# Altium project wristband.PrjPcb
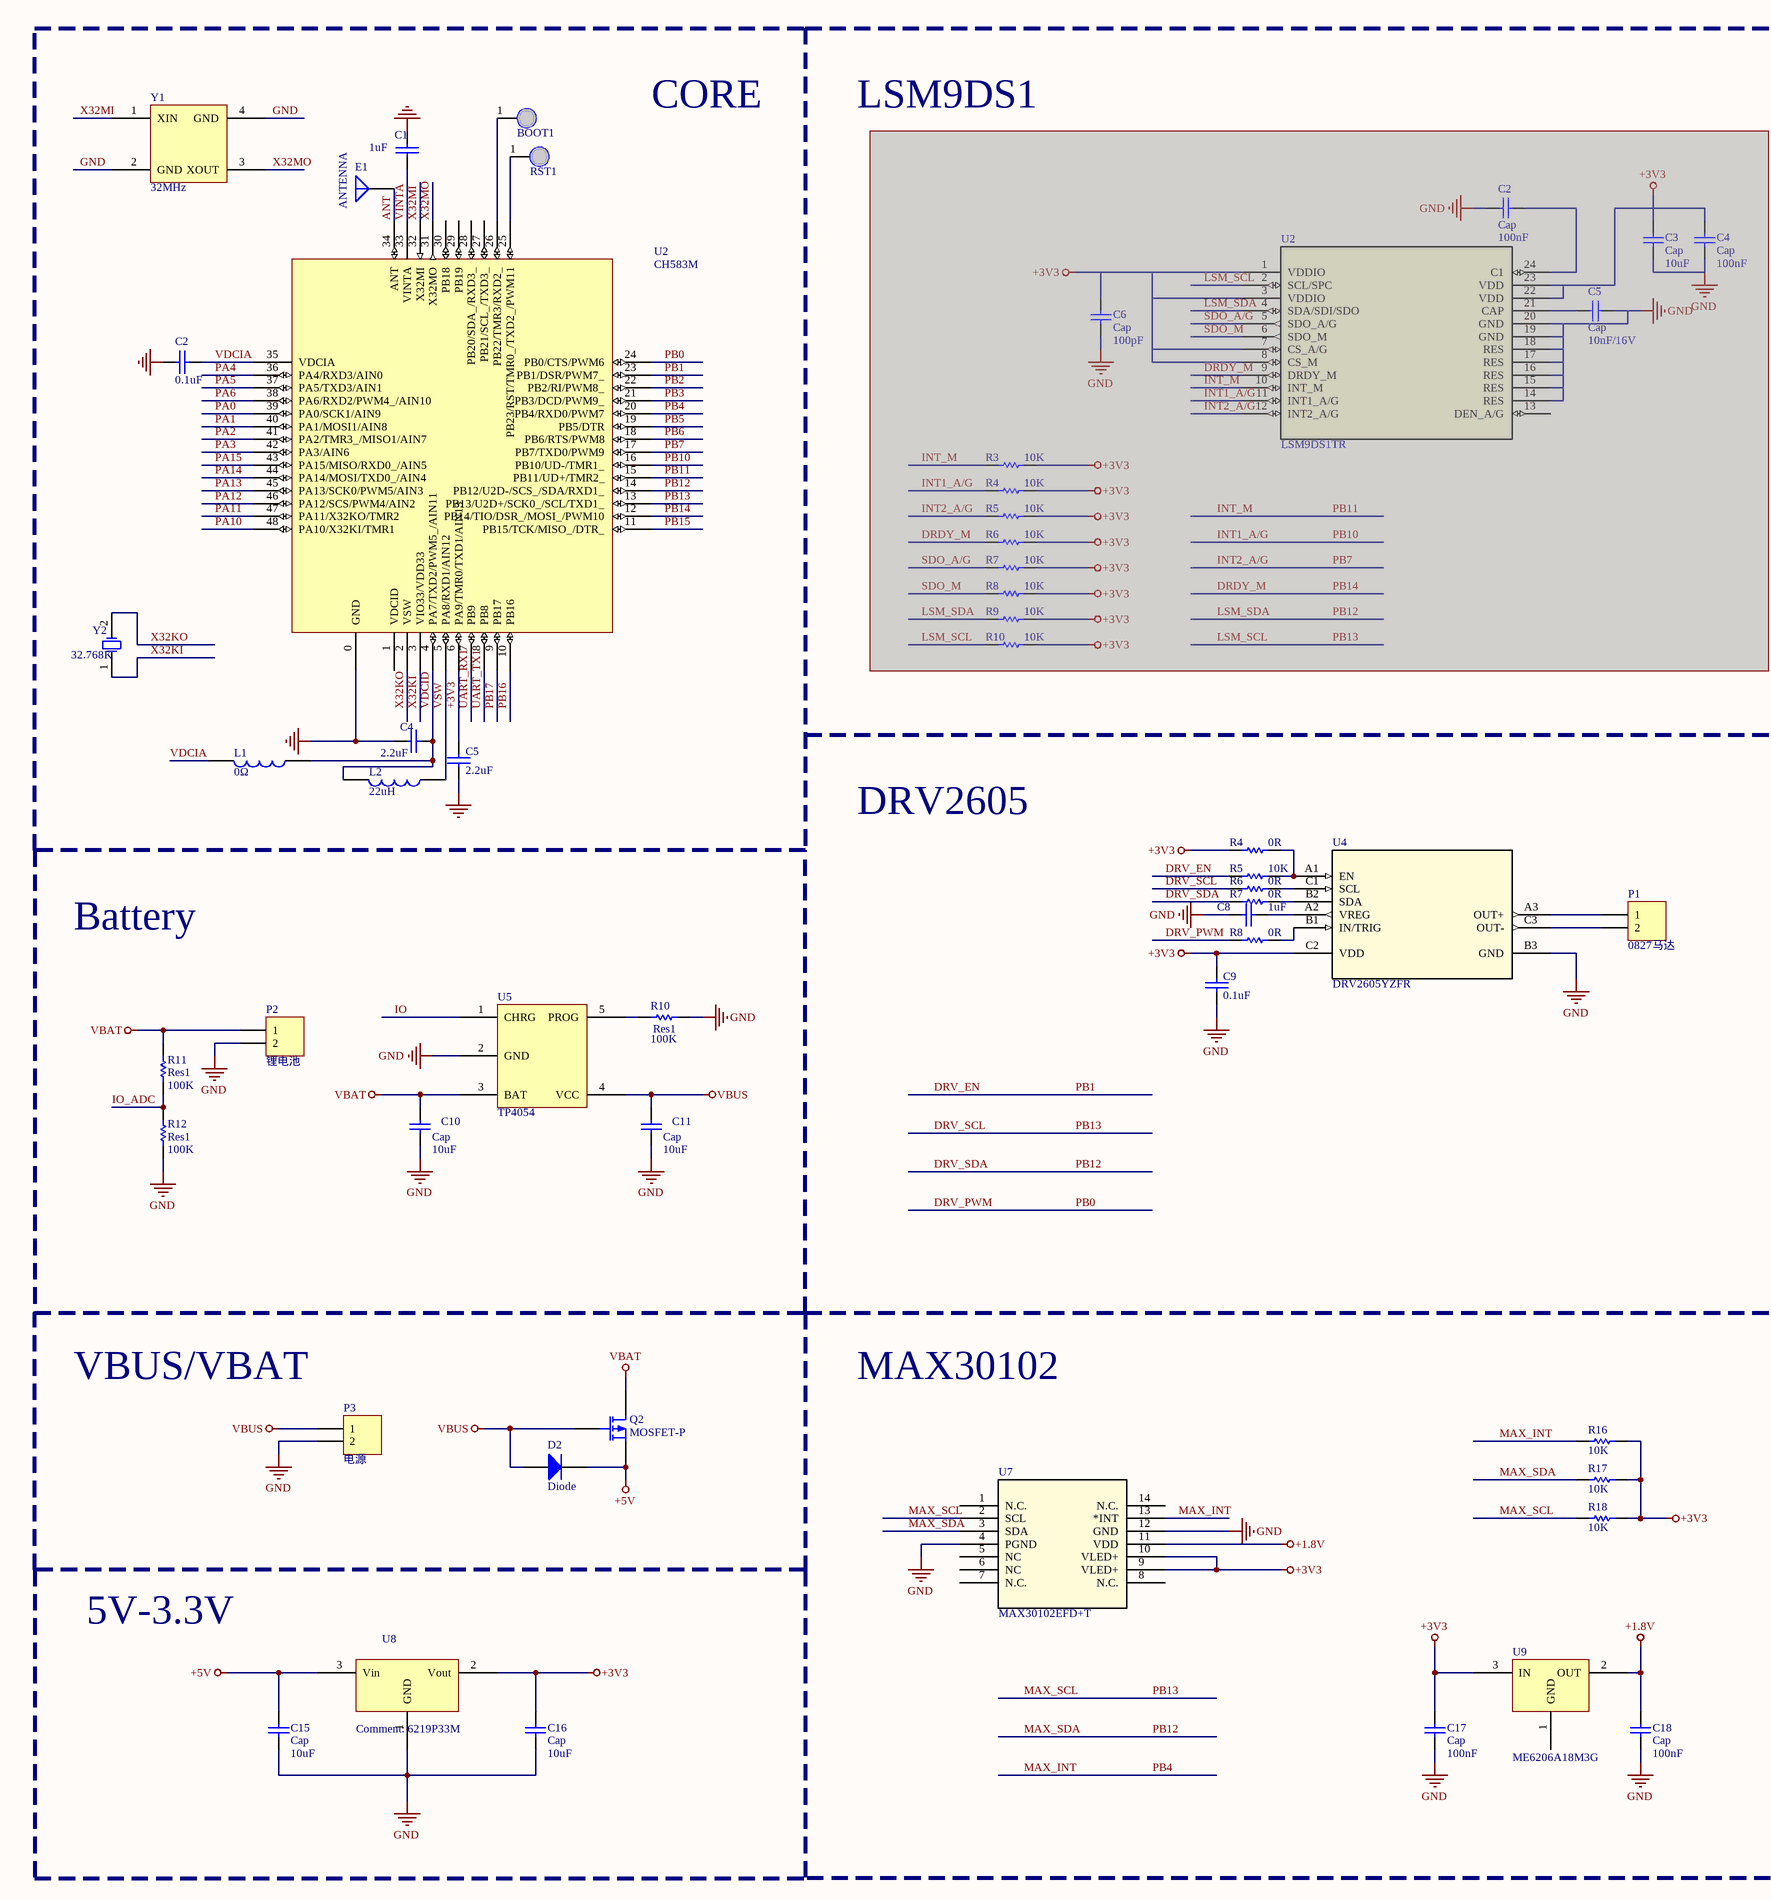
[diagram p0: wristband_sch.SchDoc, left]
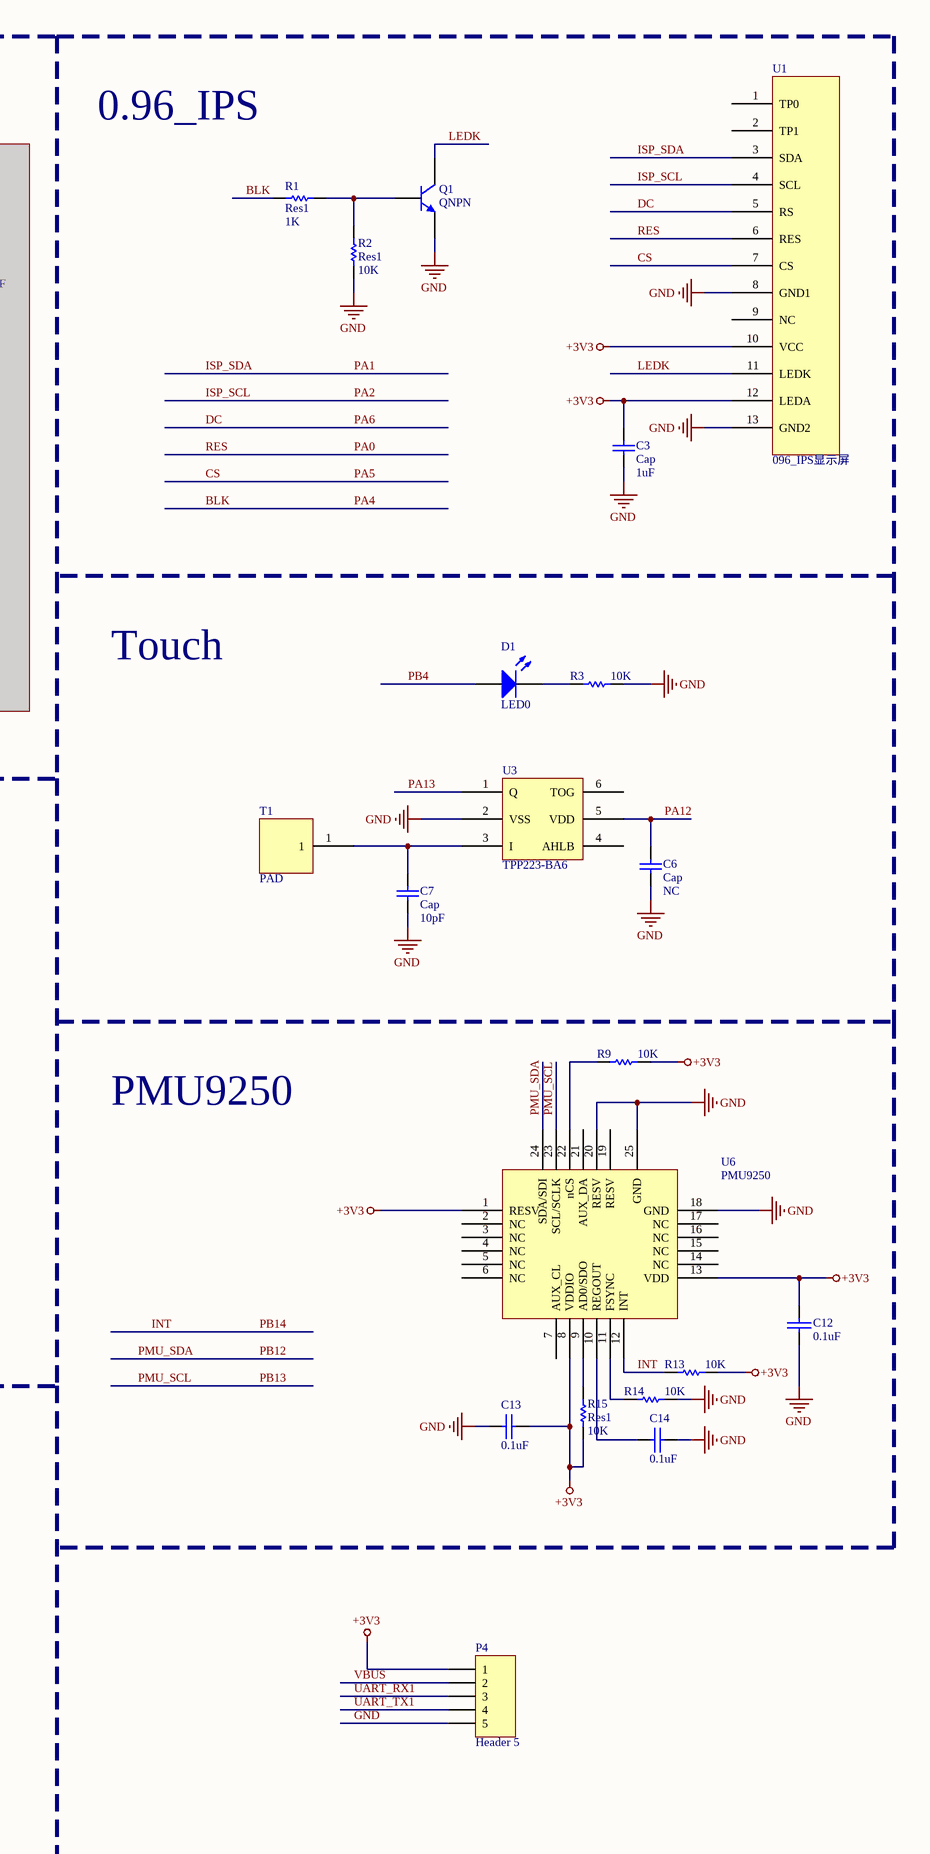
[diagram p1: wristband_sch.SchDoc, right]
1 sheet, 75 parts. Net scope: global (net labels, ports and power ports of the same name join across sheets).

## Sheet wristband_sch.SchDoc
size A2

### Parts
(Parts that share a designator on the sheet are numbered #1, #2 ... from top to bottom, then left to right.)
BOOT1  BOOT  [TESTPOINT1]  (value not drawn)
C1  1uF  [0402]
C2#1  Cap  value 100nF  [RAD-0.3]  (masked out: inside a compile mask, not in the netlist)
C2#2  0.1uF  [0402]
C3#1  Cap  value 10uF  [RAD-0.3]  (masked out: inside a compile mask, not in the netlist)
C3#2  Cap  value 1uF  [RAD-0.3]
C4#1  Cap  value 100nF  [RAD-0.3]  (masked out: inside a compile mask, not in the netlist)
C4#2  2.2uF  [0402]
C5#1  Cap  value 10nF/16V  [RAD-0.3]  (masked out: inside a compile mask, not in the netlist)
C5#2  2.2uF  [0402]
C6#1  Cap  value 100pF  [RAD-0.3]  (masked out: inside a compile mask, not in the netlist)
C6#2  Cap  value NC  [RAD-0.3]
C7  Cap  value 10pF  [RAD-0.3]
C8  1uF  [0402]
C9  0.1uF  [0402]
C10  Cap  value 10uF  [RAD-0.3]
C11  Cap  value 10uF  [RAD-0.3]
C12  0.1uF  [0402]
C13  0.1uF  [0402]
C14  0.1uF  [0402]
C15  Cap  value 10uF  [RAD-0.3]
C16  Cap  value 10uF  [RAD-0.3]
C17  Cap  value 100nF  [RAD-0.3]
C18  Cap  value 100nF  [RAD-0.3]
D1  LED0  [LED-0]
D2  Diode  [SMC]
E1  ANTENNA  [ANT-F-1-2.4G-1.6]
L1  0Ω  [0603]
L2  22uH  [L2.2]
P1  0827马达  [HDR1X2H]
P2  锂电池  [HDR1X2]
P3  电源  [HDR1X2]
P4  Header 5  [HDR1X5]
Q1  QNPN  [SOT-23B_N]
Q2  MOSFET-P  [E3]
R1  Res1  value 1K  [AXIAL-0.3]
R2  Res1  value 10K  [AXIAL-0.3]
R3#1  value 10K  [AXIAL-0.3]  (hidden comment: Res1)  (masked out: inside a compile mask, not in the netlist)
R3#2  value 10K  [AXIAL-0.3]  (hidden comment: Res1)
R4#1  value 10K  [AXIAL-0.3]  (hidden comment: Res1)  (masked out: inside a compile mask, not in the netlist)
R4#2  value 0R  [AXIAL-0.3]  (hidden comment: Res1)
R5#1  value 10K  [AXIAL-0.3]  (hidden comment: Res1)  (masked out: inside a compile mask, not in the netlist)
R5#2  value 10K  [AXIAL-0.3]  (hidden comment: Res1)
R6#1  value 10K  [AXIAL-0.3]  (hidden comment: Res1)  (masked out: inside a compile mask, not in the netlist)
R6#2  value 0R  [AXIAL-0.3]  (hidden comment: Res1)
R7#1  value 10K  [AXIAL-0.3]  (hidden comment: Res1)  (masked out: inside a compile mask, not in the netlist)
R7#2  value 0R  [AXIAL-0.3]  (hidden comment: Res1)
R8#1  value 10K  [AXIAL-0.3]  (hidden comment: Res1)  (masked out: inside a compile mask, not in the netlist)
R8#2  value 0R  [AXIAL-0.3]  (hidden comment: Res1)
R9#1  value 10K  [AXIAL-0.3]  (hidden comment: Res1)  (masked out: inside a compile mask, not in the netlist)
R9#2  value 10K  [AXIAL-0.3]  (hidden comment: Res1)
R10#1  value 10K  [AXIAL-0.3]  (hidden comment: Res1)  (masked out: inside a compile mask, not in the netlist)
R10#2  Res1  value 100K  [AXIAL-0.3]
R11  Res1  value 100K  [AXIAL-0.3]
R12  Res1  value 100K  [AXIAL-0.3]
R13  value 10K  [AXIAL-0.3]  (hidden comment: Res1)
R14  value 10K  [AXIAL-0.3]  (hidden comment: Res1)
R15  Res1  value 10K  [AXIAL-0.3]
R16  value 10K  [AXIAL-0.3]  (hidden comment: Res1)
R17  value 10K  [AXIAL-0.3]  (hidden comment: Res1)
R18  value 10K  [AXIAL-0.3]  (hidden comment: Res1)
RST1  BOOT  [TESTPOINT1]  (value not drawn)
T1  PAD
U1  096_IPS显示屏
U2#1  CH583M  [QFN48_5X5]
U2#2  LSM9DS1TR  [LGA-24_3X3P5X1_STM]  (masked out: inside a compile mask, not in the netlist)
U3  TPP223-BA6
U4  DRV2605YZFR  [YZF9]
U5  TP4054
U6  PMU9250
U7  MAX30102EFD+T  [21-1048_F143A5+1_MXM]
U8  6219P33M  [SOT-23]
U9  ME6206A18M3G
Y1  32MHz  [3225]
Y2  32.768K  [fc-135]

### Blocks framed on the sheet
CORE: BOOT1 C1 C2#2 C4#2 C5#2 E1 L1 L2 RST1 U2#1 Y1 Y2

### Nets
+1.8V: C18.1 U7.11(VDD) U9.2(OUT)
+3V3: C3#2.1 C5#2.2 C9.2 C12.2 C13.2 C16.1 C17.1 P4.1 R4#2.1 R9#2.2 R13.2 R15.2 R16.1 R17.1 R18.1 U1.10(VCC) U1.12(LEDA) U2#1.6(PA9/TMR0/TXD1/AIN13) U4.C2(VDD) U6.1(RESV) U6.8(VDDIO) U6.13(VDD) U7.9(VLED+) U7.10(VLED+) U8.2(Vout) U9.3(IN)
+5V: C15.1 D2.2(K) Q2.3(S) U8.3(Vin)
GND: C1.2 C2#2.2 C3#2.2 C4#2.1 C5#2.1 C6#2.2 C7.2 C8.1 C9.1 C10.1 C11.1 C12.1 C13.1 C14.2 C15.2 C16.2 C17.2 C18.2 P2.2 P3.2 P4.5 Q1.3(E) R2.2 R3#2.2 R10#2.2 R12.1 R14.2 U1.8(GND1) U1.13(GND2) U2#1.0(GND) U3.2(VSS) U4.B3(GND) U5.2(GND) U6.18(GND) U6.20(RESV) U6.25(GND) U7.4(PGND) U7.12(GND) U8.1(GND) Y1.2(GND) Y1.4(GND)
VBAT: C10.2 P2.1 Q2.1(D) R11.1 U5.3(BAT)
VBUS: C11.2 D2.1(A) P3.1 P4.2 Q2.2(G) U5.4(VCC)
ANT: E1.1(A) U2#1.34(ANT)
BLK: R1.2 U2#1.36(PA4/RXD3/AIN0)  [also labelled PA4]
CS: U1.7(CS) U2#1.37(PA5/TXD3/AIN1)  [also labelled PA5]
DC: U1.5(RS) U2#1.38(PA6/RXD2/PWM4_/AIN10)  [also labelled PA6]
DRV_EN: R5#2.1 U2#1.23(PB1/DSR/PWM7_)  [also labelled PB1]
DRV_PWM: R8#2.1 U2#1.24(PB0/CTS/PWM6)  [also labelled PB0]
DRV_SCL: R6#2.1 R18.2 U2#1.13(PB13/U2D+/SCK0_/SCL/TXD1_) U6.23(SCL/SCLK) U7.2(SCL)  [also labelled MAX_SCL, PB13, PMU_SCL]
DRV_SDA: R7#2.1 R17.2 U2#1.14(PB12/U2D-/SCS_/SDA/RXD1_) U6.24(SDA/SDI) U7.3(SDA)  [also labelled MAX_SDA, PB12, PMU_SDA]
INT: R13.1 U2#1.12(PB14/TIO/DSR_/MOSI_/PWM10) U6.12(INT)  [also labelled PB14]
IO: U5.1(CHRG)
IO_ADC: R11.2 R12.2
ISP_SCL: U1.4(SCL) U2#1.41(PA2/TMR3_/MISO1/AIN7)  [also labelled PA2]
ISP_SDA: U1.3(SDA) U2#1.40(PA1/MOSI1/AIN8)  [also labelled PA1]
LEDK: Q1.1(C) U1.11(LEDK)
MAX_INT: D1.1(A) R16.2 U2#1.20(PB4/RXD0/PWM7) U7.13(*INT)  [also labelled PB4]
PA0: U1.6(RES) U2#1.39(PA0/SCK1/AIN9)  [also labelled RES]
PA3: U2#1.42(PA3/AIN6)
PA10: U2#1.48(PA10/X32KI/TMR1)
PA11: U2#1.47(PA11/X32KO/TMR2)
PA12: C6#2.1 U2#1.46(PA12/SCS/PWM4/AIN2) U3.5(VDD)
PA13: U2#1.45(PA13/SCK0/PWM5/AIN3) U3.1(Q)
PA14: U2#1.44(PA14/MOSI/TXD0_/AIN4)
PA15: U2#1.43(PA15/MISO/RXD0_/AIN5)
PB2: U2#1.22(PB2/RI/PWM8_)
PB3: U2#1.21(PB3/DCD/PWM9_)
PB5: U2#1.19(PB5/DTR)
PB6: U2#1.18(PB6/RTS/PWM8)
PB7: U2#1.17(PB7/TXD0/PWM9)
PB10: U2#1.16(PB10/UD-/TMR1_)
PB11: U2#1.15(PB11/UD+/TMR2_)
PB15: U2#1.11(PB15/TCK/MISO_/DTR_)
PB16: U2#1.10(PB16)
PB17: U2#1.9(PB17)
UART_RX1: P4.3 U2#1.7(PB9)
UART_TX1: P4.4 U2#1.8(PB8)
VDCIA: C2#2.1 L1.2 U2#1.35(VDCIA)
VDCID: C4#2.2 L1.1 L2.2 U2#1.4(PA7/TXD2/PWM5_/AIN11)
VINTA: C1.1 U2#1.33(VINTA)
VSW: L2.1 U2#1.5(PA8/RXD1/AIN12)
X32KI: U2#1.3(VIO33/VDD33) Y2.1(OSC1)
X32KO: U2#1.2(VSW) Y2.2(OSC2)
X32MI: U2#1.32(X32MI) Y1.1(XIN)
X32MO: U2#1.31(X32MO) Y1.3(XOUT)
NetBOOT1_1: BOOT1.1 U2#1.26(PB22/TMR3/RXD2_)
NetC7_1: C7.1 T1.1 U3.3(I)
NetC8_2: C8.2 U4.A2(VREG)
NetC14_1: C14.1 U6.10(REGOUT)
NetD1_2: D1.2(K) R3#2.1
NetP1_1: P1.1 U4.A3(OUT+)
NetP1_2: P1.2 U4.C3(OUT-)
NetQ1_2: Q1.2(B) R1.1 R2.1
NetR4#2_2: R4#2.2 R5#2.2 U4.A1(EN)
NetR6#2_2: R6#2.2 U4.C1(SCL)
NetR7#2_2: R7#2.2 U4.B2(SDA)
NetR8#2_2: R8#2.2 U4.B1(IN/TRIG)
NetR9#2_1: R9#2.1 U6.22(nCS)
NetR10#2_1: R10#2.1 U5.5(PROG)
NetR14_1: R14.1 U6.11(FSYNC)
NetR15_1: R15.1 U6.9(AD0/SDO)
NetRST1_1: RST1.1 U2#1.25(PB23/RST/TMR0_/TXD2_/PWM11)

Not connected (* = marked no-connect by the designer): U1 1(TP0) 2(TP1) 9(NC); U2#1 1(VDCID) 27(PB21/SCL_/TXD3_) 28(PB20/SDA_/RXD3_) 29(PB19) 30(PB18); U3 4(AHLB) 6(TOG); U6 2(NC) 3(NC) 4(NC) 5(NC) 6(NC) 7(AUX_CL) 14(NC) 15(NC) 16(NC) 17(NC) 19(RESV) 21(AUX_DA); U7 1(N.C.) 5(NC) 6(NC) 7(N.C.) 8(N.C.) 14(N.C.); U9 1(GND)

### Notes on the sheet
- LSM9DS1
- 0.96_IPS
- Touch
- DRV2605
- Battery
- PMU9250
- VBUS/VBAT
- MAX30102
- 5V-3.3V

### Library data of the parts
BOOT1 RST1 = PAD 1.2MM
C1 C2#2 C4#2 C5#2 C8 C9 C12-C14 = CAP: Capacitor
C2#1 C3#1 C3#2 C4#1 C5#1 C6#1 C6#2 C7 C10 C11 C15-C18 = Cap: Capacitor
D1 = LED0: Typical INFRARED GaAs LED
D2 = Diode: Default Diode
E1 = ANTENNA: Generic Antenna
L1 L2 = INDUCTOR
P1 = Header 2H: Header, 2-Pin, Right Angle
P2 P3 = Header 2: Header, 2-Pin
P4 = Header 5: Header, 5-Pin
Q1 = QNPN: NPN Bipolar Transistor
Q2 = MOSFET-P: P-Channel MOSFET
R1 R2 R3#1 R3#2 R4#1 R4#2 R5#1 R5#2 R6#1 R6#2 R7#1 R7#2 R8#1 R8#2 R9#1 R9#2 R10#1 R10#2 R11-R18 = Res1: Resistor
U1 = Component_1
U2#1 = CH583M: RISC-V MCU with BLE/2*USB/ADC/PWM/SPI/I2C/4*UART
U2#2 = LSM9DS1TR: No Description Available; Vendor: STMicroelectronics; Built_By: EMA_Jessica; SourceLibrary: Updates_to_database_2020-11-03
U4 = DRV2605YZFR: No Description Available; Vendor: TEXAS INSTRUMENTS
U7 = MAX30102EFD+T: No Description Available; SourceLibrary: Update_to_database_2021-01-29; Built_By: EMA_UL_Team; Vendor: Maxim Integrated Products
Y1 = 晶体
Y2 = XTAL: Crystal Oscillator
